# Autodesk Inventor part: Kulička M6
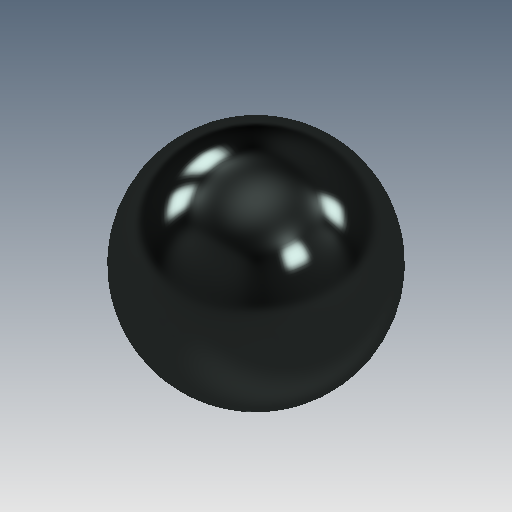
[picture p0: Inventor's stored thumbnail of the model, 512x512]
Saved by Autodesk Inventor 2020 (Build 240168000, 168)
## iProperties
Created: 2025-04
Part Number: Kulička M6
Material: ABS plast
Document SubType Name: Modeling
Designer: doma
Density: 1.06 g/cm^3
Appearance: Dělovina – leštěná
Mass: 2.01649 g
Surface Area: 9.7419 cm^2
Volume: 1.90235 cm^3
Author: doma
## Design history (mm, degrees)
sketch "Náčrt1"
  geometry: L1 (0, 8)-(16, 8); A1 r 8 centre (8, 8) between (0, 8) and (16, 8); 1 further point
  constraints: 2 end point, 2 point on circle, 1 centre point, 1 horizontal
  dimensions: "d0" = 16 diameter of A1; "d1" = 8 horizontal distance of point (0, 0) A1.centre; "d2" = 8 horizontal distance of point (0, 0) A1.centre
revolve "Rotace1" sketch "Náčrt1" stored, may be unused: angle "d3" = 90 deg
sketch "Náčrt2"
  geometry: L1 (1, -11.71)-(1, 16.254); 4 further points
  constraints: 2 end point, 1 vertical, 1 other
  dimensions: "d5" = 1 distance from line of point (0, 0) L1
extrude "Vysunutí1" cut sketch "Náčrt2" extent not by distance; stored distance "d6" = 11.034; taper "d7" = 0 deg
sketch "Náčrt3"
  geometry: 2 further points
hole "Díra1" sketch "Náčrt3" at (0, 0) diameter "d8" = 4.917; stored, may be unused: countersink angle "d12" = 90 deg, drill point angle "d14" = 118 deg; dims "d9" = 11, "d10" = 4, "d11" = 2, "d13" = 11
node "Těleso1"
